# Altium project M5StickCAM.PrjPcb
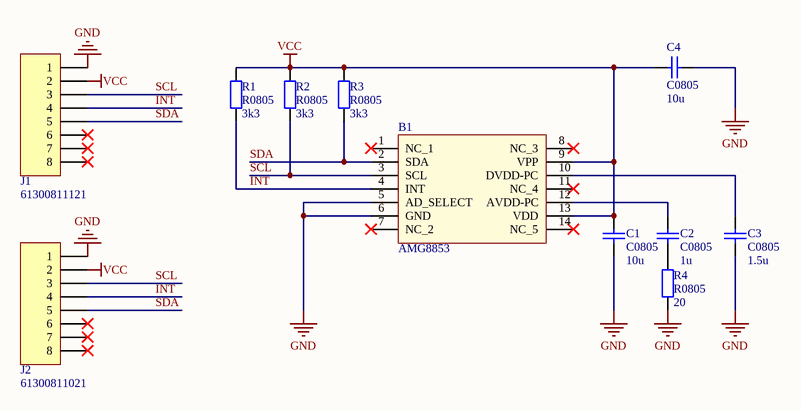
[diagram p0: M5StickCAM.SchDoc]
author: a; Author: DZE
1 sheet, 11 parts. Net scope: global (net labels, ports and power ports of the same name join across sheets).
Board file: M5StickGridEye.PcbDoc

## Sheet M5StickCAM.SchDoc
size A4; Organization: Altium Limited; Address1: L3, 12a Rodborough Rd; Address2: Frenchs Forest; Address3: NSW; Address4: Australia 2086

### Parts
B1  AMG8853  [AMG8853]
C1  C0805  value 10u  [C0805]
C2  C0805  value 1u  [C0805]
C3  C0805  value 1.5u  [C0805]
C4  C0805  value 10u  [C0805]
J1  61300811121  [61300811121]
J2  61300811021  [61300811021]
R1  R0805  value 3k3  [R0805]
R2  R0805  value 3k3  [R0805]
R3  R0805  value 3k3  [R0805]
R4  R0805  value 20  [R0805]

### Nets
GND: B1.5(AD_SELECT) B1.6(GND) C1.1 C3.1 C4.1 J1.1 J2.1 R4.1
VCC: B1.9(VPP) B1.13(VDD) C1.2 C4.2 J1.2 J2.2 R1.2 R2.2 R3.2
INT: B1.4(INT) J1.4 J2.4 R1.1
SCL: B1.3(SCL) J1.3 J2.3 R2.1
SDA: B1.2(SDA) J1.5 J2.5 R3.1
NetB1_10: B1.10(DVDD-PC) C3.2
NetB1_12: B1.12(AVDD-PC) C2.2
NetC2_1: C2.1 R4.2

Not connected (* = marked no-connect by the designer): B1 1(NC_1)* 7(NC_2)* 8(NC_3)* 11(NC_4)* 14(NC_5)*; J1 6* 7* 8*; J2 6* 7* 8*

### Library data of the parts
B1 = AMG8853: IR Array Sensor Grid-EYE,5V,High gain Panasonic AMG8853 Grid-EYE Proximity Sensor Infrared Array Sensor, 7m, Maximum of 5 V dc 14-Pin
C1-C4 = C0805: Capacitor
J1 = 61300811121: WR-PHD 2.54 mm THT Pin Header, 08p
J2 = 61300811021: WR-PHD 2.54 mm THT Angled Pin Header, 08p
R1-R4 = R0805: Resistor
